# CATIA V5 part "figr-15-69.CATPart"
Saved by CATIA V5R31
Part number: Part1
Bounding box of the stored display mesh (mm): x -110.541 to 53, y 0 to 2, z -29.652 to 29.652
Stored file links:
  D:\PROJECTS\Project 2021\US EDITION\CATIA V5 6R 2021\Resources\Part Files\c15_catia_v5_6r2021_prt\figr-15-69.CATPart
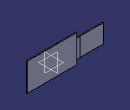
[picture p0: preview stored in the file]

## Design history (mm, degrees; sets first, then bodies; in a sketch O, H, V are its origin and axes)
SheetMetalParameters1: Thickness 2, BendRadius 4, KFactor 0.400515 {= log(min(100,max(20*SheetMetalParameters1.BendRadius,SheetMetalParameters1.Thickness)/SheetMetalParameters1.Thickness))/log(100)/2}, ReliefRadialLength 1, ReliefAxialLength 2, MinimumBendRadius 0
Body1 (main body)
  Sketch1 on zx-plane, origin (0, 0, 0), H (-1, 0, 0), V (0, 0, 1)
    line L1 (53, 29.6521) -> (53, -29.6521)
    line L2 (53, -29.6521) -> (-53, -29.6521)
    line L3 (-53, -29.6521) -> (-53, 29.6521)
    line L4 (-53, 29.6521) -> (53, 29.6521)
    vertical: L1 V, L3 V
    horizontal: L2 H, L4 H
    equidistance: L1 L3 O, L2 L4 O
  Wall1: Thickness 2, Profile Sketch1, OffsetValue 0
  Plane1: type Offset, RefPlane face of Wall1, Offset 10
  Plane2: type Offset, RefPlane face of Wall1, Offset 10
  Flange1: Angle 90, Length 50, Radius 4 {= SheetMetalParameters1.BendRadius}, KFacteur 0.400515 {= log(min(100,max(20*Flange1.Radius,SheetMetalParameters1.Thickness)/SheetMetalParameters1.Thickness))/log(100)/2}, Guide edge [face of Wall1 | face of Wall1], Limit1 Plane1, Limit2 Plane2
  Unfold1: FoldUnfold_Angles 90, FoldUnfold_FoldUnfoldFaces face of Flange1, FoldUnfold_ReferenceFaces face of Wall1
